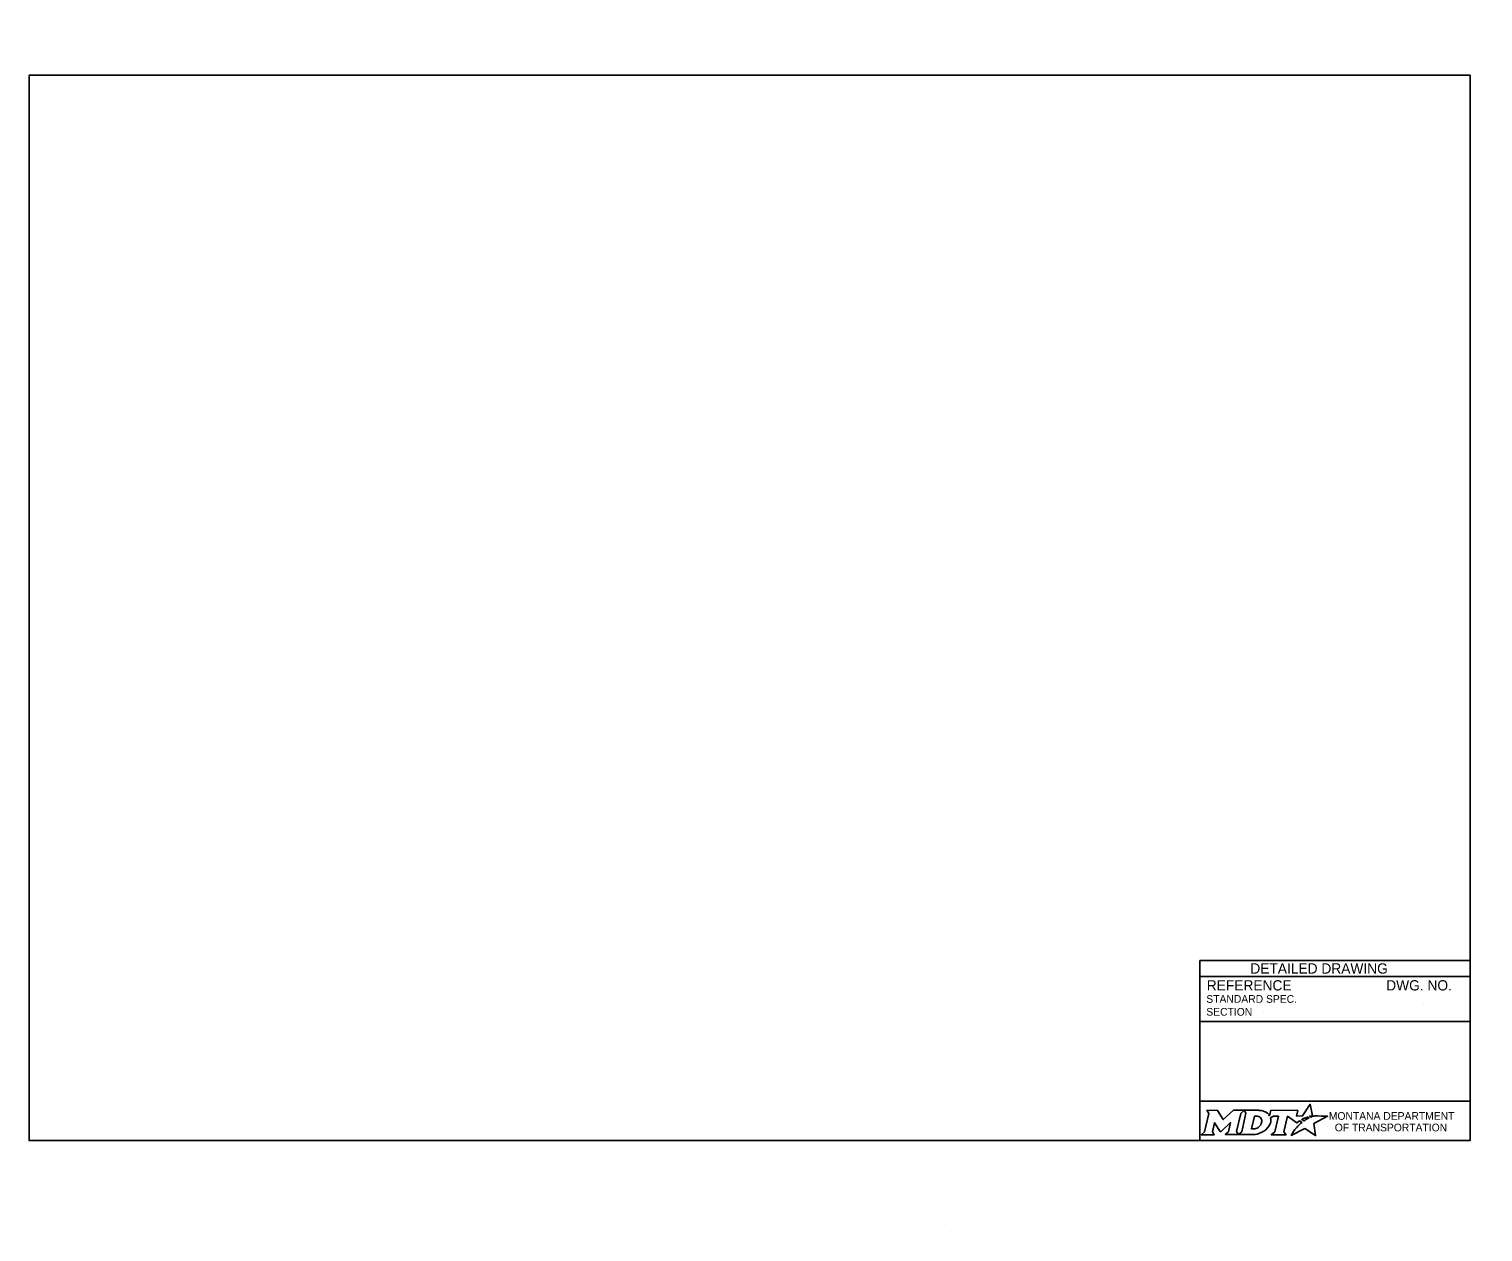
# Model space of a CAD drawing. Extents: x 49991.4 to 50070, y 49987.6 to 50011.4.
# Drawn here: x 50009.74 to 50021.04, y 49999.18 to 50008.52 of the extents above; entities that cross this region are included whole.
import ezdxf

# ---------------------------------------------------------------- set-up
doc = ezdxf.new("R2010")
doc.units = 0
for name, color, linetype in [('Default', 7, 'Continuous'), ('Level 1', 7, 'Continuous'), ('Level 4', 7, 'Continuous')]:
    doc.layers.add(name, color=color, linetype=linetype)

msp = doc.modelspace()

# ---------------------------------------------------------------- linework, layer by layer
at = {"layer": 'Default'}
for points in [[(50019.7, 50000.068), (50019.69, 50000.074), (50019.702, 50000.076), (50019.713, 50000.078), (50019.696, 50000.168), (50019.636, 50000.077), (50019.589, 50000.076), (50019.599, 50000.12), (50019.39, 50000.121), (50019.38, 50000.078), (50019.374, 50000.086)], [(50018.893, 50000.121), (50018.907, 50000.097), (50018.874, 49999.954), (50018.848, 49999.931), (50018.95, 49999.931), (50018.936, 49999.954), (50018.952, 50000.024), (50018.996, 49999.955), (50019.002, 49999.955), (50019.077, 50000.025), (50019.06, 49999.954), (50019.035, 49999.932), (50019.137, 49999.932), (50019.123, 49999.955), (50019.156, 50000.097)], [(50019.156, 50000.097), (50019.182, 50000.121), (50019.099, 50000.121), (50019.02, 50000.048), (50018.975, 50000.12), (50018.893, 50000.121)], [(50019.295, 50000.121), (50019.182, 50000.121), (50019.196, 50000.098), (50019.163, 49999.954), (50019.137, 49999.932), (50019.248, 49999.932)], [(50019.319, 50000.034), (50019.318, 50000.026), (50019.315, 50000.017), (50019.311, 50000.008), (50019.305, 50000.001), (50019.299, 49999.994), (50019.291, 49999.988), (50019.282, 49999.983), (50019.273, 49999.979), (50019.264, 49999.977), (50019.255, 49999.976), (50019.239, 49999.976), (50019.263, 50000.076), (50019.279, 50000.076), (50019.286, 50000.075), (50019.294, 50000.073), (50019.301, 50000.07), (50019.307, 50000.066), (50019.311, 50000.061), (50019.315, 50000.055), (50019.318, 50000.049), (50019.319, 50000.042), (50019.32, 50000.038), (50019.319, 50000.034)], [(50019.387, 50000.062), (50019.411, 50000.075), (50019.448, 50000.075), (50019.42, 49999.954), (50019.392, 49999.931), (50019.508, 49999.931), (50019.491, 49999.954), (50019.52, 50000.075), (50019.591, 50000.023), (50019.612, 50000.038), (50019.632, 50000.027)], [(50019.576, 49999.971), (50019.561, 49999.947), (50019.556, 49999.939), (50019.55, 49999.931), (50019.548, 49999.926), (50019.653, 49999.979), (50019.737, 49999.924), (50019.724, 50000.017), (50019.831, 50000.075), (50019.782, 50000.076), (50019.751, 50000.077), (50019.731, 50000.077), (50019.724, 50000.075), (50019.719, 50000.074), (50019.711, 50000.072), (50019.7, 50000.068)], [(50019.65, 50000.04), (50019.648, 50000.039), (50019.629, 50000.048), (50019.639, 50000.054), (50019.644, 50000.056), (50019.652, 50000.06), (50019.658, 50000.063), (50019.666, 50000.066), (50019.673, 50000.068), (50019.685, 50000.061), (50019.681, 50000.059), (50019.676, 50000.056), (50019.672, 50000.054), (50019.667, 50000.051), (50019.665, 50000.05), (50019.662, 50000.049), (50019.66, 50000.047), (50019.658, 50000.046), (50019.655, 50000.044), (50019.652, 50000.042), (50019.65, 50000.04)], [(50019.293, 49999.939), (50019.302, 49999.942), (50019.315, 49999.947), (50019.335, 49999.958)], [(50019.59, 49999.987), (50019.59, 49999.987)]]:
    msp.add_lwpolyline(points, dxfattribs=at)
for centre, radius, start, end in [((50019.319, 50000.042), 0.0709, 339.5329, 15.8582), ((50019.274, 50000.059), 0.118, 300.9103, 339.1383)]:
    msp.add_arc(centre, radius, start, end, dxfattribs=at)
for centre, major_axis, ratio, start_param, end_param in [((50019.293, 50000.073), (0.0834, -0.0037), 0.568097, 0.61298, 1.570796), ((50019.349, 50000.081), (0.0361, -0.0295), 0.469099, 1.225588, 1.570796), ((50019.621, 50000.017), (-0.0112, -0.0097), 0.021651, 3.157348, 6.283185), ((50019.248, 50000.08), (0, 0.148), 0.987302, 3.139398, 3.456847), ((50019.583, 49999.979), (-0.00694, -0.00806), 0.008222, 0, 3.137361), ((50019.6, 49999.997), (-0.0098, -0.0102), 0.016458, 3.141593, 6.279097)]:
    msp.add_ellipse(centre, major_axis=major_axis, ratio=ratio, start_param=start_param, end_param=end_param, dxfattribs=at)
at = {"layer": 'Level 1'}
for p, q in [((50021.038, 50008.524), (50021.038, 50008.524)), ((50016.9, 49999.176), (50016.9, 49999.176))]:
    msp.add_line(p, q, dxfattribs=at)
msp.add_lwpolyline([(50020.938, 50008.165), (50009.737, 50008.165), (50009.737, 49999.886), (50020.938, 49999.886)], close=True, dxfattribs=at)
at = {"layer": 'Level 4'}
for p, q in [((50020.938, 50001.286), (50018.838, 50001.286)), ((50018.838, 50001.286), (50018.838, 49999.886)), ((50020.938, 50001.161), (50018.838, 50001.161)), ((50020.574, 50000.946), (50020.574, 50000.946)), ((50020.938, 50000.811), (50018.838, 50000.811)), ((50019.332, 50000.886), (50019.332, 50000.886)), ((50019.888, 50000.562), (50019.888, 50000.562)), ((50020.938, 50000.193), (50018.838, 50000.193))]:
    msp.add_line(p, q, dxfattribs=at)

# ---------------------------------------------------------------- texts
at = {"layer": 'Default'}
for s, p in [('MONTANA DEPARTMENT', (50019.84, 50000.047)), ('OF TRANSPORTATION', (50019.886, 49999.957))]:
    msp.add_text(s, height=0.06, rotation=360, dxfattribs=at).set_placement(p)
at = {"layer": 'Level 4'}
for s, height, p in [('DETAILED DRAWING', 0.0799, (50019.23, 50001.183)), ('REFERENCE', 0.08, (50018.891, 50001.052)), ('DWG. NO.', 0.08, (50020.286, 50001.052)), ('STANDARD SPEC.', 0.06, (50018.888, 50000.956)), ('SECTION', 0.06, (50018.888, 50000.856))]:
    msp.add_text(s, height=height, dxfattribs=at).set_placement(p)

doc.saveas('drawing.dxf')
